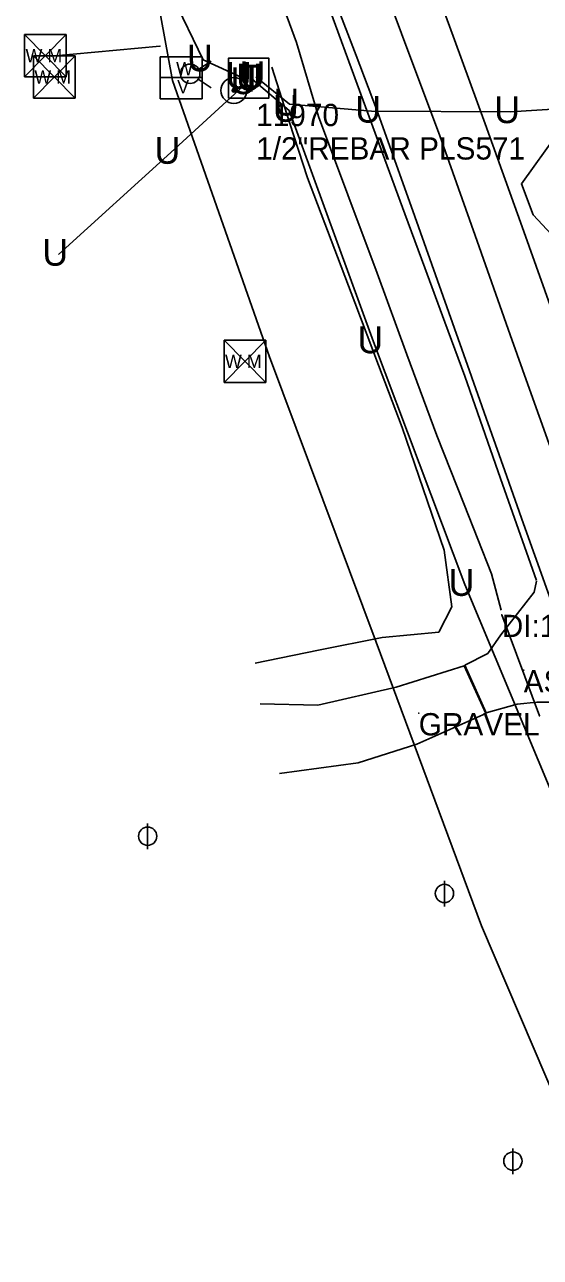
# Model space of a CAD drawing. Extents: x 1050807 to 1053552, y 395828 to 398415.
# Drawn here: x 1051999.2 to 1052115, y 397522.9 to 397799.4 of the extents above; entities that cross this region are included whole.
import ezdxf

# ---------------------------------------------------------------- set-up
doc = ezdxf.new("R2010")
doc.units = 0
for name, color, linetype in [('Default', 7, 'Continuous'), ('S_CROSS_DRAIN', 7, 'Continuous'), ('S_CROSS_DRAIN_ANNOT', 7, 'Continuous'), ('S_DITCHLINE', 7, 'Continuous'), ('S_DRG_PT_SYM', 7, 'Continuous'), ('S_DRIVEWAY', 7, 'Continuous'), ('S_EDGE_PAVEMENT', 7, 'Continuous'), ('S_IRON_PIN', 7, 'Continuous'), ('S_IRON_PIN_ANNOT', 7, 'Continuous'), ('S_MSC_PT_SYM', 7, 'Continuous'), ('S_PAVEMENT_CROWN', 7, 'Continuous'), ('S_SHOULDER', 7, 'Continuous'), ('S_SURVEY_TEXT_ANNOT', 7, 'Continuous'), ('S_TELEPHONE_UTILITIES', 7, 'Continuous'), ('S_UNDERGROUND_CABLE', 7, 'Continuous'), ('S_UTILITY_POLE', 7, 'Continuous'), ('S_UTL_PT_SYM', 7, 'Continuous'), ('S_WATER_UTILITIES', 7, 'Continuous')]:
    doc.layers.add(name, color=color, linetype=linetype)

msp = doc.modelspace()

# ---------------------------------------------------------------- linework, layer by layer
at = {"layer": 'S_CROSS_DRAIN'}
msp.add_line((1052106.29, 397667.04), (1052114.76, 397644.4), dxfattribs=at)
at = {"layer": 'S_DITCHLINE'}
msp.add_lwpolyline([(1052106.17, 397668.06), (1052103.97, 397676.24), (1052097.83, 397691.75), (1052091.69, 397707.25), (1052084.99, 397725.46), (1052078.3, 397743.68), (1052071.74, 397761.24), (1052065.18, 397778.8), (1052060.21, 397795.41), (1052056.36, 397805.99)], dxfattribs=at)
at = {"layer": 'S_DRG_PT_SYM'}
for points in [[(1052106.29, 397667.04), (1052106.29, 397667.09), (1052106.29, 397667.04), (1052106.24, 397667.04), (1052106.29, 397667.04), (1052106.29, 397666.99), (1052106.29, 397667.04), (1052106.34, 397667.04)], [(1052114.76, 397644.4), (1052114.76, 397644.45), (1052114.76, 397644.4), (1052114.71, 397644.4), (1052114.76, 397644.4), (1052114.76, 397644.35), (1052114.76, 397644.4), (1052114.81, 397644.4)]]:
    msp.add_lwpolyline(points, dxfattribs=at)
at = {"layer": 'S_DRIVEWAY'}
for points in [[(1052054.66, 397789.87), (1052058.69, 397777.47), (1052062.73, 397765.06), (1052068.03, 397751.06), (1052073.33, 397737.06), (1052078.62, 397723.06), (1052083.92, 397709.06), (1052088.65, 397695.29), (1052093.39, 397681.53), (1052095.08, 397668.82), (1052092.16, 397663.15), (1052079.45, 397661.95), (1052065.18, 397659.09), (1052050.92, 397656.23)], [(1052056.43, 397631.43), (1052074.07, 397633.85), (1052087.21, 397637.99), (1052102.74, 397644.88), (1052097.86, 397655.61), (1052082.58, 397650.84), (1052065.04, 397646.81), (1052052.08, 397647.07)]]:
    msp.add_lwpolyline(points, dxfattribs=at)
at = {"layer": 'S_EDGE_PAVEMENT'}
for points in [[(1052214.47, 397461.1), (1052206.55, 397483.78), (1052198.62, 397506.45), (1052191.75, 397526.31), (1052184.88, 397546.16), (1052177.39, 397567.38), (1052169.89, 397588.61), (1052165.61, 397600.65), (1052161.33, 397612.68), (1052157.05, 397624.72), (1052152.78, 397636.76), (1052148.47, 397648.84), (1052144.17, 397660.93), (1052139.87, 397673.02), (1052135.57, 397685.11), (1052127.35, 397708.02), (1052119.13, 397730.93), (1052110.86, 397754.03), (1052102.59, 397777.13), (1052095.71, 397795.99), (1052088.82, 397814.85)], [(1052196.26, 397454.39), (1052187.61, 397477.79), (1052178.96, 397501.18), (1052174.52, 397513.15), (1052170.08, 397525.12), (1052165.65, 397537.09), (1052161.21, 397549.06), (1052156.87, 397561), (1052152.53, 397572.94), (1052148.19, 397584.89), (1052143.85, 397596.83), (1052135.54, 397619.78), (1052127.24, 397642.73), (1052119.19, 397665.09), (1052111.15, 397687.46), (1052106.97, 397699.31), (1052102.79, 397711.16), (1052098.61, 397723.02), (1052094.43, 397734.87), (1052086.32, 397757.66), (1052078.21, 397780.45), (1052073.59, 397792.48), (1052068.98, 397804.51)], [(1052131.61, 397701.92), (1052130.86, 397715.11), (1052144.6, 397722.59), (1052138.9, 397739), (1052133.2, 397755.41), (1052125.14, 397752.48), (1052117.48, 397752.33), (1052113.34, 397756.77), (1052110.71, 397763.72), (1052118.88, 397775.06), (1052122.78, 397778.38), (1052139.51, 397788.91), (1052158.09, 397798.17), (1052174.27, 397801.39)], [(1052123.83, 397647.43), (1052114.18, 397647.48), (1052109.74, 397646.97), (1052102.81, 397645.04), (1052098.03, 397655.71), (1052103.13, 397658.35), (1052106.07, 397662.52), (1052113.6, 397672.12), (1052114.07, 397674.6)]]:
    msp.add_lwpolyline(points, dxfattribs=at)
at = {"layer": 'S_IRON_PIN'}
for radius in [2.91, 0.411, 0.262, 0.212, 0.145, 0.0822, 0.0581]:
    msp.add_circle((1052046.18, 397784.65), radius, dxfattribs=at)
at = {"layer": 'S_MSC_PT_SYM'}
for points in [[(1052111.21, 397654.63), (1052111.21, 397654.68), (1052111.21, 397654.63), (1052111.16, 397654.63), (1052111.21, 397654.63), (1052111.21, 397654.58), (1052111.21, 397654.63), (1052111.26, 397654.63)], [(1052087.66, 397644.99), (1052087.66, 397645.04), (1052087.66, 397644.99), (1052087.61, 397644.99), (1052087.66, 397644.99), (1052087.66, 397644.94), (1052087.66, 397644.99), (1052087.71, 397644.99)]]:
    msp.add_lwpolyline(points, dxfattribs=at)
at = {"layer": 'S_PAVEMENT_CROWN'}
msp.add_lwpolyline([(1052205.81, 397457.74), (1052201.49, 397469.54), (1052197.18, 397481.35), (1052192.86, 397493.15), (1052188.55, 397504.96), (1052180.47, 397527.64), (1052172.39, 397550.33), (1052164.11, 397573.46), (1052155.84, 397596.59), (1052149.3, 397615.07), (1052142.77, 397633.56), (1052138.44, 397645.49), (1052134.12, 397657.43), (1052129.8, 397669.37), (1052125.47, 397681.31), (1052121.16, 397693.43), (1052116.84, 397705.56), (1052112.53, 397717.68), (1052108.21, 397729.81), (1052100.29, 397752.14), (1052092.37, 397774.47), (1052083.81, 397797.39), (1052075.25, 397820.32)], dxfattribs=at)
at = {"layer": 'S_SHOULDER'}
msp.add_lwpolyline([(1052114.06, 397674.75), (1052106.02, 397697.65), (1052097.99, 397720.54), (1052093.51, 397732.69), (1052089.03, 397744.85), (1052084.54, 397757), (1052080.06, 397769.15), (1052073.84, 397786.05), (1052067.62, 397802.95)], dxfattribs=at)
at = {"layer": 'S_TELEPHONE_UTILITIES'}
msp.add_lwpolyline([(1052044.99, 397782.91), (1052044.99, 397791.91), (1052053.99, 397791.91), (1052053.99, 397782.91)], close=True, dxfattribs=at)
at = {"layer": 'S_UNDERGROUND_CABLE'}
for p, q in [((1052039.29, 397791.49), (1052025.92, 397819.22)), ((1052047.99, 397787.58), (1052039.29, 397791.49)), ((1052049.09, 397786.37), (1052031.99, 397770.74)), ((1052058.57, 397780.16), (1052050.31, 397787.18)), ((1052051.07, 397787.72), (1052058.68, 397781.58)), ((1052108.22, 397779.87), (1052160.23, 397783.16)), ((1052077.52, 397728.26), (1052058.57, 397780.16)), ((1052058.68, 397781.58), (1052077.03, 397779.99)), ((1052077.03, 397779.99), (1052108.22, 397779.87)), ((1052031.99, 397770.74), (1052006.83, 397747.89)), ((1052098, 397673.83), (1052077.52, 397728.26)), ((1052121.65, 397617.16), (1052098, 397673.83))]:
    msp.add_line(p, q, dxfattribs=at)
at = {"layer": 'S_UTILITY_POLE'}
for p, q in [((1052026.82, 397614.45), (1052026.82, 397620.23)), ((1052093.43, 397601.61), (1052093.43, 397607.39)), ((1052108.79, 397541.58), (1052108.79, 397547.37))]:
    msp.add_line(p, q, dxfattribs=at)
for centre in [(1052026.82, 397617.38), (1052093.43, 397604.54), (1052108.79, 397544.51)]:
    msp.add_circle(centre, 2.05, dxfattribs=at)
at = {"layer": 'S_UTL_PT_SYM'}
for points in [[(1052029.58, 397794.57), (1052029.58, 397794.62), (1052029.58, 397794.57), (1052029.53, 397794.57), (1052029.58, 397794.57), (1052029.58, 397794.52), (1052029.58, 397794.57), (1052029.63, 397794.57)], [(1052005.26, 397792.37), (1052005.26, 397792.42), (1052005.26, 397792.37), (1052005.21, 397792.37), (1052005.26, 397792.37), (1052005.26, 397792.32), (1052005.26, 397792.37), (1052005.31, 397792.37)], [(1052032.43, 397786.88), (1052032.43, 397786.93), (1052032.43, 397786.88), (1052032.38, 397786.88), (1052032.43, 397786.88), (1052032.43, 397786.83), (1052032.43, 397786.88), (1052032.48, 397786.88)], [(1052054.15, 397724.87), (1052054.15, 397724.92), (1052054.15, 397724.87), (1052054.09, 397724.87), (1052054.15, 397724.87), (1052054.15, 397724.82), (1052054.15, 397724.87), (1052054.2, 397724.87)], [(1052078.14, 397660.91), (1052078.14, 397660.96), (1052078.14, 397660.91), (1052078.09, 397660.91), (1052078.14, 397660.91), (1052078.14, 397660.86), (1052078.14, 397660.91), (1052078.19, 397660.91)], [(1052101.72, 397597.26), (1052101.72, 397597.31), (1052101.72, 397597.26), (1052101.67, 397597.26), (1052101.72, 397597.26), (1052101.72, 397597.21), (1052101.72, 397597.26), (1052101.77, 397597.26)]]:
    msp.add_lwpolyline(points, dxfattribs=at)
at = {"layer": 'S_WATER_UTILITIES'}
for p, q in [((1052032.43, 397786.88), (1052022.97, 397838.59)), ((1051999.22, 397797.2), (1052008.56, 397797.2)), ((1051999.22, 397797.2), (1051999.22, 397787.71)), ((1051999.22, 397797.2), (1052008.56, 397787.71)), ((1052008.56, 397797.2), (1051999.22, 397787.71)), ((1052008.56, 397797.2), (1052008.56, 397787.71)), ((1052005.26, 397792.37), (1052029.58, 397794.57)), ((1052001.19, 397792.43), (1052010.53, 397792.43)), ((1052001.19, 397792.43), (1052001.19, 397782.94)), ((1052001.19, 397792.43), (1052010.53, 397782.94)), ((1052010.53, 397792.43), (1052001.19, 397782.94)), ((1052010.53, 397792.43), (1052010.53, 397782.94)), ((1052029.65, 397792.21), (1052039.07, 397792.21)), ((1052029.65, 397782.8), (1052029.65, 397792.21)), ((1052038.28, 397789.46), (1052041.1, 397791.19)), ((1052039.07, 397792.21), (1052039.07, 397782.8)), ((1051999.22, 397787.71), (1052008.56, 397787.71)), ((1052029.65, 397787.52), (1052039.07, 397787.52)), ((1052054.15, 397724.87), (1052032.43, 397786.88)), ((1052038.15, 397787.15), (1052041.06, 397785.22)), ((1052001.19, 397782.94), (1052010.53, 397782.94)), ((1052039.07, 397782.8), (1052029.65, 397782.8)), ((1052043.98, 397728.63), (1052053.32, 397728.63)), ((1052043.98, 397728.63), (1052043.98, 397719.14)), ((1052043.98, 397728.63), (1052053.32, 397719.14)), ((1052053.32, 397728.63), (1052043.98, 397719.14)), ((1052053.32, 397728.63), (1052053.32, 397719.14)), ((1052078.14, 397660.91), (1052054.15, 397724.87)), ((1052043.98, 397719.14), (1052053.32, 397719.14)), ((1052101.72, 397597.26), (1052078.14, 397660.91)), ((1052119.03, 397556.83), (1052101.72, 397597.26))]:
    msp.add_line(p, q, dxfattribs=at)
msp.add_circle((1052036.37, 397788.4), 2.18, dxfattribs=at)

# ---------------------------------------------------------------- texts
at = {"layer": 'Default'}
for p in [(1052035.67, 397788.94), (1052047.44, 397785.17), (1052044.36, 397785.03), (1052045.46, 397783.82), (1052046.69, 397784.64), (1052054.94, 397777.62), (1052055.05, 397779.03), (1052073.4, 397777.44), (1052104.59, 397777.32), (1052028.36, 397768.2), (1052003.2, 397745.34), (1052073.9, 397725.71), (1052094.37, 397671.29)]:
    msp.add_text('U', height=6, dxfattribs=at).set_placement(p)
at = {"layer": 'S_CROSS_DRAIN_ANNOT'}
msp.add_text('DI:18" LN:23\' TY:CMP CN:50%', height=5, dxfattribs=at).set_placement((1052106.29, 397662.04))
at = {"layer": 'S_IRON_PIN_ANNOT'}
for s, p in [('11970', (1052051.18, 397776.65)), ('1/2"REBAR PLS571', (1052051.18, 397769.15))]:
    msp.add_text(s, height=5, dxfattribs=at).set_placement(p)
at = {"layer": 'S_SURVEY_TEXT_ANNOT'}
for s, p in [('ASPHLT APRON', (1052111.21, 397649.63)), ('GRAVEL DRIVE', (1052087.66, 397639.99))]:
    msp.add_text(s, height=5, dxfattribs=at).set_placement(p)
at = {"layer": 'S_TELEPHONE_UTILITIES'}
msp.add_text('T', height=6, dxfattribs=at).set_placement((1052047.55, 397784.41))
at = {"layer": 'S_WATER_UTILITIES'}
for s, p in [('W M', (1051999.42, 397790.97)), ('W M', (1052001.4, 397786.2)), ('W', (1052033.21, 397788.06)), ('V', (1052033.44, 397783.99)), ('W M', (1052044.18, 397722.4))]:
    msp.add_text(s, height=3, dxfattribs=at).set_placement(p)

doc.saveas('drawing.dxf')
